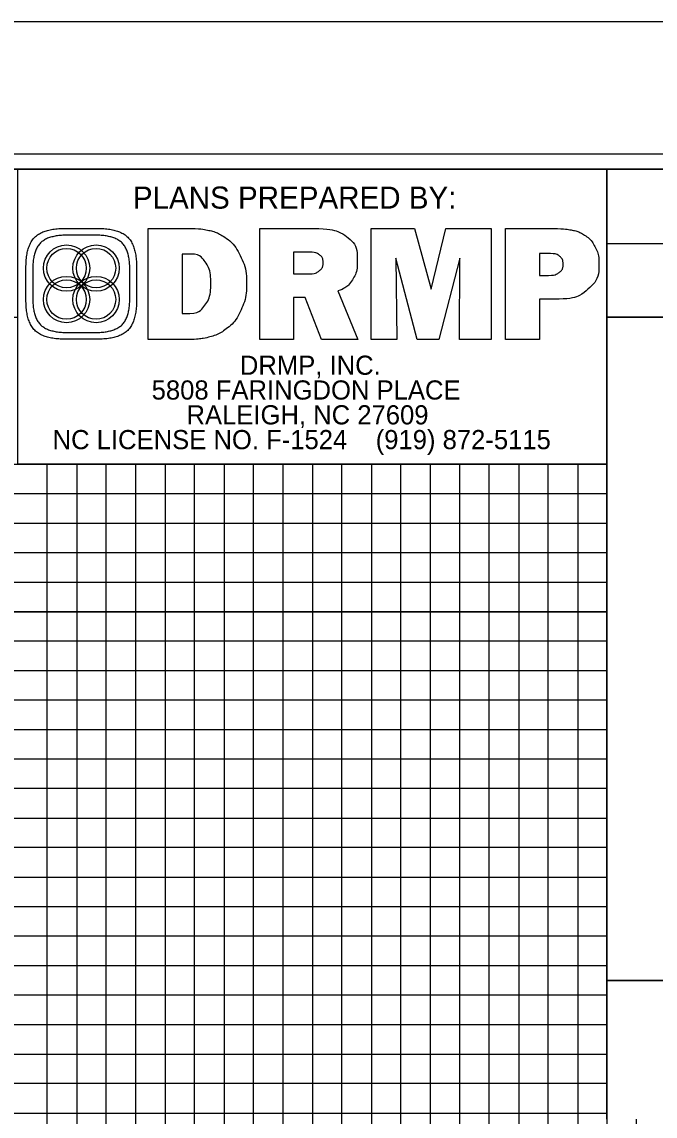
# Model space of a CAD drawing. Extents: x 1263639 to 1265460, y 747271 to 748371.
# Drawn here: x 1265006.4 to 1265113.9, y 748185.2 to 748370.7 of the extents above; entities that cross this region are included whole.
import ezdxf

# ---------------------------------------------------------------- set-up
doc = ezdxf.new("R2010")
doc.units = 0
for name, color, linetype in [('Pattern 1', 7, 'Continuous'), ('Pattern 2', 7, 'Continuous'), ('Prop Drainage Structure Bridge Opening', 7, 'Continuous'), ('Prop Grid Mask', 7, 'Continuous'), ('Prop Horizontal Alignment', 7, 'Continuous'), ('Prop Paved Shoulder', 7, 'Continuous'), ('Prop PFL Text', 7, 'Continuous'), ('Prop Terminator CELL', 7, 'Continuous'), ('Prop VPI Label', 7, 'Continuous'), ('Sheet Block System Information CELL', 7, 'Continuous'), ('Sheet Layout Plan Border', 7, 'Continuous'), ('Sheet Project Info Box CELL', 7, 'Continuous'), ('Sheet Sticker Exception Certification CELL', 7, 'Continuous')]:
    doc.layers.add(name, color=color, linetype=linetype)

msp = doc.modelspace()

# ---------------------------------------------------------------- linework, layer by layer
at = {"layer": 'Pattern 1'}
for points in [[(1265105.7, 748270.74), (1263805.85, 748270.74), (1263805.85, 748320.69), (1265005.75, 748320.69)], [(1265055.75, 748295.74), (1265055.75, 747320.74), (1265105.75, 747320.74), (1265105.75, 748295.74)], [(1265305.75, 748170.74), (1263805.75, 748170.74), (1263805.75, 748220.74), (1265105.7, 748220.74)]]:
    msp.add_lwpolyline(points, dxfattribs=at)
at = {"layer": 'Pattern 2'}
for points in [[(1263805.75, 748295.74), (1265105.7, 748295.74)], [(1265030.75, 748295.74), (1265030.75, 747320.74), (1265080.75, 747320.74), (1265080.75, 748295.74)], [(1265105.7, 748245.74), (1263805.75, 748245.74), (1263805.75, 748195.69), (1265105.7, 748195.69)]]:
    msp.add_lwpolyline(points, dxfattribs=at)
at = {"layer": 'Prop Drainage Structure Bridge Opening'}
msp.add_line((1265322.75, 748370.74), (1263638.75, 748370.74), dxfattribs=at)
at = {"layer": 'Prop Grid Mask'}
msp.add_lwpolyline([(1263855.75, 748345.74), (1265105.7, 748345.74), (1265105.75, 747320.74), (1263855.75, 747320.74)], close=True, dxfattribs=at)
at = {"layer": 'Prop Horizontal Alignment'}
msp.add_lwpolyline([(1265105.7, 748345.74), (1265105.7, 748295.74), (1265005.75, 748295.74), (1265005.75, 748345.74)], close=True, dxfattribs=at)
msp.add_lwpolyline([(1265105.7, 748345.74), (1265105.7, 748295.74), (1265005.75, 748295.74), (1265005.75, 748345.74)], close=True, dxfattribs=at)
at = {"layer": 'Prop Paved Shoulder'}
msp.add_line((1265105.7, 748333.19), (1265305.75, 748333.19), dxfattribs=at)
for points in [[(1265305.75, 748345.74), (1263805.75, 748345.74), (1263805.75, 747295.74), (1265305.75, 747295.74)], [(1265105.7, 748345.74), (1265305.75, 748345.74), (1265305.75, 748320.69), (1265105.7, 748320.69)], [(1265105.7, 748320.69), (1265205.75, 748320.69), (1265205.75, 748208.19), (1265105.7, 748208.19)]]:
    msp.add_lwpolyline(points, close=True, dxfattribs=at)
at = {"layer": 'Prop PFL Text'}
for p, q in [((1265055.75, 748295.74), (1265055.75, 747320.74)), ((1263805.75, 748270.74), (1265105.7, 748270.74)), ((1263805.75, 748220.74), (1265105.7, 748220.74)), ((1265105.75, 747320.74), (1265105.75, 748208.19))]:
    msp.add_line(p, q, dxfattribs=at)
at = {"layer": 'Prop Terminator CELL'}
msp.add_lwpolyline([(1265318.25, 748348.29), (1263651.75, 748348.29), (1263651.75, 747293.19), (1265318.25, 747293.19)], close=True, dxfattribs=at)
at = {"layer": 'Prop VPI Label'}
msp.add_lwpolyline([(1265322.75, 748370.74), (1263638.75, 748370.74), (1263638.75, 747270.74), (1265322.75, 747270.74)], close=True, dxfattribs=at)
at = {"layer": 'Sheet Block System Information CELL'}
for centre, radius in [((1265014.03, 748328.99), 3.93), ((1265014.03, 748328.99), 3.34), ((1265019.03, 748328.99), 3.93), ((1265019.03, 748328.99), 3.34), ((1265014.03, 748323.66), 3.93), ((1265014.03, 748323.66), 3.34), ((1265019.03, 748323.66), 3.93), ((1265019.03, 748323.66), 3.34)]:
    msp.add_circle(centre, radius, dxfattribs=at)
at = {"layer": 'Sheet Layout Plan Border'}
for p, q in [((1265105.7, 748184.69), (1265105.7, 748208.19)), ((1265105.7, 748208.19), (1265305.74, 748208.19))]:
    msp.add_line(p, q, dxfattribs=at)
at = {"layer": 'Sheet Project Info Box CELL'}
for p, q in [((1265013.81, 748335.72), (1265019.26, 748335.72)), ((1265065.69, 748316.9), (1265065.69, 748335.7)), ((1265065.69, 748335.7), (1265073.08, 748335.7)), ((1265073.08, 748335.7), (1265075.9, 748325.43)), ((1265075.9, 748325.43), (1265078.38, 748335.7)), ((1265078.38, 748335.7), (1265086.1, 748335.7)), ((1265086.1, 748335.7), (1265086.1, 748316.9)), ((1265018.92, 748334.57), (1265014.14, 748334.57)), ((1265073.54, 748316.9), (1265069.89, 748330.69)), ((1265069.89, 748330.69), (1265070.08, 748316.9)), ((1265080.77, 748330.69), (1265077.19, 748316.9)), ((1265080.68, 748316.9), (1265080.77, 748330.69)), ((1265007.14, 748323.6), (1265007.14, 748329.05)), ((1265008.29, 748328.72), (1265008.29, 748323.94)), ((1265024.77, 748323.94), (1265024.77, 748328.72)), ((1265025.92, 748329.05), (1265025.92, 748323.6)), ((1265014.14, 748318.08), (1265018.92, 748318.08)), ((1265019.26, 748316.94), (1265013.81, 748316.94)), ((1265070.08, 748316.9), (1265065.69, 748316.9)), ((1265077.19, 748316.9), (1265073.54, 748316.9)), ((1265086.1, 748316.9), (1265080.68, 748316.9))]:
    msp.add_line(p, q, dxfattribs=at)
for points in [[(1265034.84, 748316.9), (1265027.86, 748316.9), (1265027.86, 748335.7), (1265035.09, 748335.7)], [(1265060.08, 748325.12), (1265063.47, 748316.9), (1265057.29, 748316.9), (1265054.51, 748324.03), (1265052.54, 748324.03), (1265052.54, 748316.9), (1265046.82, 748316.9), (1265046.82, 748335.7), (1265056, 748335.7)], [(1265097.59, 748323.75), (1265094.25, 748323.75), (1265094.25, 748316.9), (1265088.49, 748316.9), (1265088.49, 748335.7), (1265096.5, 748335.7)], [(1265035.09, 748331.38), (1265033.62, 748331.38), (1265033.62, 748321.3), (1265034.92, 748321.3)], [(1265055.19, 748331.69), (1265052.54, 748331.69), (1265052.54, 748328.01), (1265055.27, 748328.01)], [(1265096.15, 748331.45), (1265094.25, 748331.45), (1265094.25, 748327.76), (1265095.8, 748327.76)]]:
    msp.add_lwpolyline(points, dxfattribs=at)
for points, degree in [([(1265007.14, 748329.05), (1265007.14, 748332.72), (1265010.14, 748335.72), (1265013.81, 748335.72)], 2), ([(1265019.26, 748335.72), (1265022.92, 748335.72), (1265025.92, 748332.72), (1265025.92, 748329.05)], 2), ([(1265035.09, 748335.7), (1265036.23, 748335.7), (1265037.25, 748335.6), (1265038.15, 748335.39), (1265039.05, 748335.19), (1265039.83, 748334.88), (1265040.51, 748334.45), (1265041.79, 748333.64), (1265042.79, 748332.53), (1265043.5, 748331.1), (1265044.21, 748329.68), (1265044.57, 748328.08), (1265044.57, 748326.31), (1265044.57, 748324.74), (1265044.26, 748323.27), (1265043.63, 748321.9), (1265043, 748320.54), (1265042.15, 748319.45), (1265041.07, 748318.64), (1265040.27, 748318.05), (1265039.36, 748317.61), (1265038.35, 748317.33), (1265037.34, 748317.05), (1265036.17, 748316.9), (1265034.84, 748316.9)], 3), ([(1265056, 748335.7), (1265058.46, 748335.7), (1265060.3, 748335.24), (1265061.53, 748334.33), (1265062.75, 748333.42), (1265063.36, 748332.04), (1265063.36, 748330.21), (1265063.36, 748328.94), (1265063.08, 748327.87), (1265062.52, 748326.99), (1265061.96, 748326.12), (1265061.15, 748325.49), (1265060.08, 748325.12)], 3), ([(1265096.5, 748335.7), (1265097.76, 748335.7), (1265098.8, 748335.62), (1265099.62, 748335.47), (1265100.44, 748335.31), (1265101.13, 748335.07), (1265101.68, 748334.73), (1265102.56, 748334.18), (1265103.23, 748333.48), (1265103.68, 748332.63), (1265104.14, 748331.78), (1265104.36, 748330.82), (1265104.36, 748329.74), (1265104.36, 748327.95), (1265103.74, 748326.51), (1265102.5, 748325.41), (1265101.25, 748324.3), (1265099.62, 748323.75), (1265097.59, 748323.75)], 3), ([(1265014.14, 748334.57), (1265010.92, 748334.57), (1265008.29, 748331.93), (1265008.29, 748328.72)], 2), ([(1265024.77, 748328.72), (1265024.77, 748331.93), (1265022.14, 748334.57), (1265018.92, 748334.57)], 2), ([(1265034.92, 748321.3), (1265036, 748321.3), (1265036.86, 748321.76), (1265037.51, 748322.69), (1265038.16, 748323.61), (1265038.49, 748324.85), (1265038.49, 748326.39), (1265038.49, 748327.92), (1265038.18, 748329.13), (1265037.56, 748330.03), (1265036.95, 748330.93), (1265036.13, 748331.38), (1265035.09, 748331.38)], 3), ([(1265055.27, 748328.01), (1265055.94, 748328.01), (1265056.49, 748328.18), (1265056.91, 748328.53), (1265057.33, 748328.87), (1265057.55, 748329.31), (1265057.55, 748329.85), (1265057.55, 748330.47), (1265057.35, 748330.93), (1265056.96, 748331.23), (1265056.57, 748331.53), (1265055.98, 748331.69), (1265055.19, 748331.69)], 3), ([(1265095.8, 748327.76), (1265096.58, 748327.76), (1265097.18, 748327.93), (1265097.62, 748328.25), (1265098.05, 748328.58), (1265098.27, 748329.03), (1265098.27, 748329.61), (1265098.27, 748330.2), (1265098.08, 748330.66), (1265097.72, 748330.98), (1265097.36, 748331.29), (1265096.84, 748331.45), (1265096.15, 748331.45)], 3), ([(1265013.81, 748316.94), (1265010.14, 748316.94), (1265007.14, 748319.94), (1265007.14, 748323.6)], 2), ([(1265008.29, 748323.94), (1265008.29, 748320.72), (1265010.92, 748318.08), (1265014.14, 748318.08)], 2), ([(1265018.92, 748318.08), (1265022.14, 748318.08), (1265024.77, 748320.72), (1265024.77, 748323.94)], 2), ([(1265025.92, 748323.6), (1265025.92, 748319.94), (1265022.92, 748316.94), (1265019.26, 748316.94)], 2)]:
    msp.add_open_spline(points, degree=degree, dxfattribs=at)
at = {"layer": 'Sheet Sticker Exception Certification CELL'}
for points in [[(1265010.75, 747320.74), (1265010.75, 748295.74)], [(1265015.75, 748295.74), (1265015.75, 747320.74), (1265020.75, 747320.74), (1265020.75, 748295.74)], [(1265025.75, 748295.74), (1265025.75, 747320.74), (1265035.75, 747320.74), (1265035.75, 748295.74)], [(1265040.75, 748295.74), (1265040.75, 747320.74), (1265045.75, 747320.74), (1265045.75, 748295.74)], [(1265050.75, 748295.74), (1265050.75, 747320.74), (1265060.75, 747320.74), (1265060.75, 748295.74)], [(1265065.75, 748295.74), (1265065.75, 747320.74), (1265070.75, 747320.74), (1265070.75, 748295.74)], [(1265075.75, 748295.74), (1265075.75, 747320.74), (1265085.75, 747320.74), (1265085.75, 748295.74)], [(1265090.75, 748295.74), (1265090.75, 747320.74), (1265095.75, 747320.74), (1265095.75, 748295.74)], [(1265100.75, 748295.74), (1265100.75, 747320.74), (1265110.75, 747320.74), (1265110.75, 748184.69)], [(1265105.7, 748290.74), (1263855.75, 748290.74), (1263855.75, 748285.74), (1265105.7, 748285.74)], [(1265105.7, 748280.74), (1263855.75, 748280.74), (1263855.75, 748275.74), (1265105.7, 748275.74)], [(1265105.7, 748265.74), (1263855.75, 748265.74), (1263855.75, 748260.74), (1265105.7, 748260.74)], [(1265105.7, 748255.74), (1263855.75, 748255.74), (1263855.75, 748250.74), (1265105.7, 748250.74)], [(1265105.7, 748240.74), (1263855.75, 748240.74), (1263855.75, 748235.74), (1265105.7, 748235.74)], [(1265105.7, 748230.74), (1263855.75, 748230.74), (1263855.75, 748225.74), (1265105.7, 748225.74)], [(1265105.7, 748215.74), (1263855.75, 748215.74), (1263855.75, 748210.74), (1265105.7, 748210.74)], [(1265105.7, 748205.74), (1263855.75, 748205.74), (1263855.75, 748205.74), (1263855.75, 748185.74), (1265105.7, 748185.74)], [(1263855.75, 748200.74), (1265105.7, 748200.74)], [(1265105.7, 748190.74), (1263855.75, 748190.74)]]:
    msp.add_lwpolyline(points, dxfattribs=at)

# ---------------------------------------------------------------- texts
at = {"layer": 'Sheet Block System Information CELL'}
msp.add_text('PLANS PREPARED BY:', height=3.75, rotation=360, dxfattribs=at).set_placement((1265025.28, 748339.07))
for s, p in [('DRMP, INC.', (1265043.44, 748310.9)), ('5808 FARINGDON PLACE', (1265028.47, 748306.7)), ('RALEIGH, NC 27609', (1265034.38, 748302.49)), ('NC LICENSE NO. F-1524    (919) 872-5115', (1265011.66, 748298.29))]:
    msp.add_text(s, height=3.25, dxfattribs=at).set_placement(p)

doc.saveas('drawing.dxf')
